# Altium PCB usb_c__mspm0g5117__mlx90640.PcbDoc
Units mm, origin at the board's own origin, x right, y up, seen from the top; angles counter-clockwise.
Board outline 64 x 33 mm, 2 copper layers (Top, Bottom), stack 0 mm thick; 27 components, 19 nets, 155 pads, 66 vias.
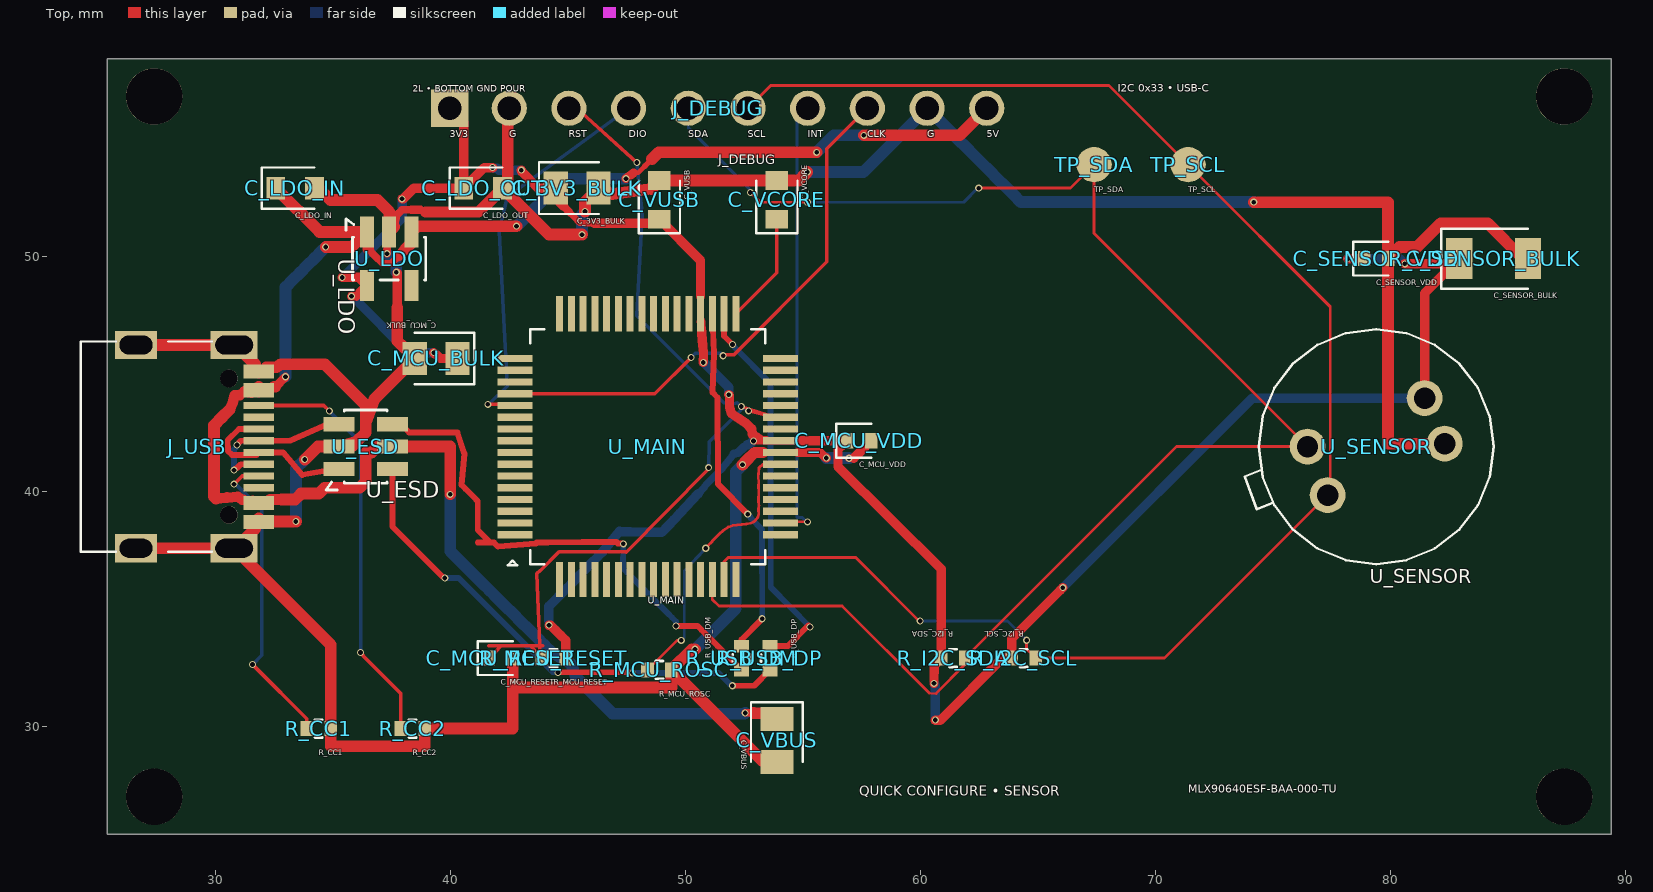
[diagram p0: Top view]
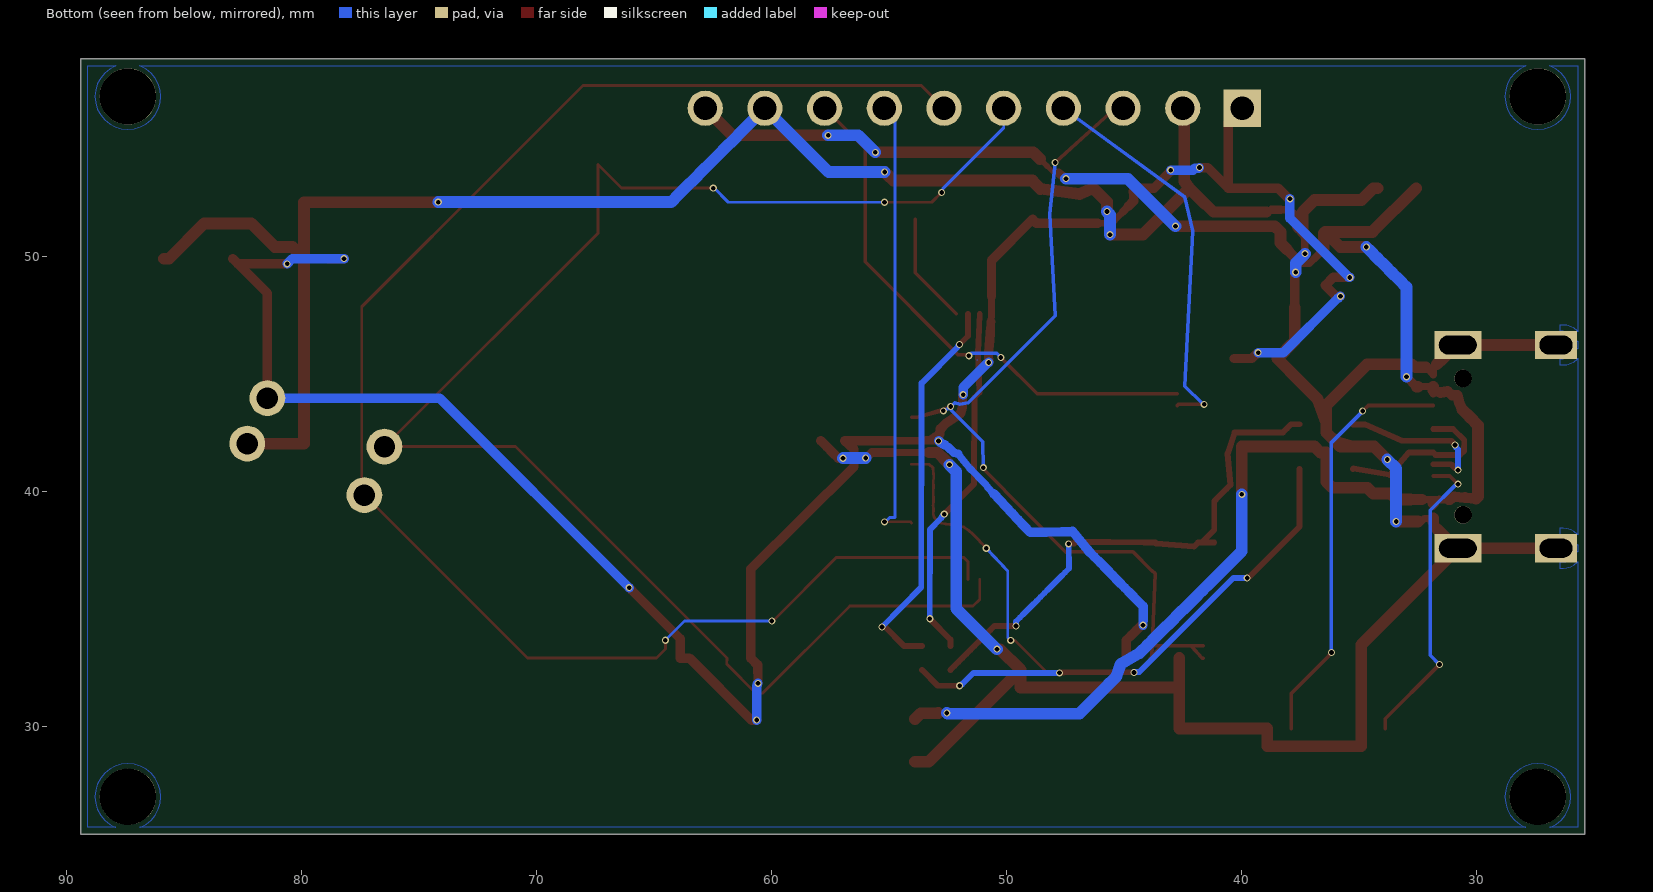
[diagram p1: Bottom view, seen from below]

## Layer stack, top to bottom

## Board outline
25.4,58.4 89.4,58.4 89.4,25.4 25.4,25.4

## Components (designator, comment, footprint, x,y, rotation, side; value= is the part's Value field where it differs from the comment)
C_3V3_BULK "" TSCIRCUIT-2.8500x1.4000mm 45.4,52.9 r0 top
C_LDO_IN "" TSCIRCUIT-2.4500x0.9500mm 33.4,52.9 r0 top
C_LDO_OUT "" TSCIRCUIT-2.4500x0.9500mm 41.4,52.9 r0 top
C_MCU_BULK "" TSCIRCUIT-2.8500x1.4000mm 39.4,45.65 r180 top
C_MCU_RESET "" TSCIRCUIT-1.5600x0.6400mm 42.15,32.9 r0 top
C_MCU_VDD "" TSCIRCUIT-1.5600x0.6400mm 57.4,42.15 r0 top
C_SENSOR_BULK "" TSCIRCUIT-4.0500x1.7500mm 84.4,49.9 r0 top
C_SENSOR_VDD "" TSCIRCUIT-1.5600x0.6400mm 79.4,49.9 r0 top
C_VBUS "" TSCIRCUIT-1.4000x2.8500mm 53.9,29.4 r270 top
C_VCORE "" TSCIRCUIT-0.9500x2.4500mm 53.9,52.4 r90 top
C_VUSB "" TSCIRCUIT-0.9500x2.4500mm 48.9,52.4 r90 top
J_DEBUG "" TSCIRCUIT-24.3600x1.5000mm 51.4,56.3 r0 top
J_USB "" TSCIRCUIT-6.7732x9.8502mm 29.112,41.9 r90 top
R_CC1 "" TSCIRCUIT-1.5600x0.6400mm 34.4,29.9 r0 top
R_CC2 "" TSCIRCUIT-1.5600x0.6400mm 38.4,29.9 r0 top
R_I2C_SCL "" TSCIRCUIT-1.5600x0.6400mm 64.4,32.9 r180 top
R_I2C_SDA "" TSCIRCUIT-1.5600x0.6400mm 61.4,32.9 r180 top
R_MCU_RESET "" TSCIRCUIT-1.5600x0.6400mm 44.4,32.9 r0 top
R_MCU_ROSC "" TSCIRCUIT-1.5600x0.6400mm 48.9,32.4 r0 top
R_USB_DM "" TSCIRCUIT-0.6400x1.5600mm 52.4,32.9 r90 top
R_USB_DP "" TSCIRCUIT-0.6400x1.5600mm 53.6,32.9 r90 top
TP_SCL "" TSCIRCUIT-1.5000x1.5000mm 71.4,53.9 r0 top
TP_SDA "" TSCIRCUIT-1.5000x1.5000mm 67.4,53.9 r0 top
U_ESD "" TSCIRCUIT-3.6000x2.5000mm 36.4,41.9 r0 top
U_LDO "" TSCIRCUIT-2.5000x3.6000mm 37.4,49.9 r270 top
U_MAIN "" TSCIRCUIT-12.8000x12.8000mm 48.4,41.9 r0 top
U_SENSOR "" TSCIRCUIT-7.3640x5.6538mm 79.4,41.9 r0 top

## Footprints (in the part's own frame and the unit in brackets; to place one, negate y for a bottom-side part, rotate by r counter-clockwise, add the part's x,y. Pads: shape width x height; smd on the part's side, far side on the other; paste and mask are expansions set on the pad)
TSCIRCUIT-0.6400x1.5600mm [mm]
  rect 0.54x0.64 smd: 1(-0.51,0) 2(0.51,0)
  silkscreen extent -0.15,-0.38 0.15,0.38
TSCIRCUIT-0.9500x2.4500mm [mm]
  rect 0.8x0.95 smd: 1(-0.825,0) 2(0.825,0)
  silkscreen extent -1.42,-0.88 0.82,0.87
TSCIRCUIT-1.4000x2.8500mm [mm]
  rect 1.025x1.4 smd: 1(-0.913,0) 2(0.913,0)
  silkscreen extent -1.63,-1.1 0.91,1.1
TSCIRCUIT-1.5000x1.5000mm [mm]
  round 1.5 smd: 1(0,0)
TSCIRCUIT-1.5600x0.6400mm [mm]
  rect 0.54x0.64 smd: 1(-0.51,0) 2(0.51,0)
  silkscreen extent -0.98,-0.72 0.51,0.72
TSCIRCUIT-2.4500x0.9500mm [mm]
  rect 0.8x0.95 smd: 1(-0.825,0) 2(0.825,0)
  silkscreen extent -1.42,-0.88 0.82,0.87
TSCIRCUIT-2.5000x3.6000mm [mm]
  rect 1.325x0.6 smd: 1(-1.138,-0.95) 2(-1.138,0) 3(-1.138,0.95) 4(1.137,0.95) 5(1.137,-0.95)
  silkscreen extent -1.69,-1.84 0.91,1.56
TSCIRCUIT-2.8500x1.4000mm [mm]
  rect 1.025x1.4 smd: 1(-0.913,0) 2(0.913,0)
  silkscreen extent -1.63,-1.1 0.91,1.1
TSCIRCUIT-3.6000x2.5000mm [mm]
  rect 1.325x0.6 smd: 1(-1.138,-0.95) 2(-1.138,0) 3(-1.138,0.95) 4(1.137,0.95) 5(1.137,0) 6(1.137,-0.95)
  silkscreen extent -1.69,-1.84 0.91,1.56
TSCIRCUIT-4.0500x1.7500mm [mm]
  rect 1.125x1.75 smd: 1(-1.462,0) 2(1.463,0)
  silkscreen extent -2.22,-1.27 1.46,1.28
TSCIRCUIT-6.7732x9.8502mm [mm]
  rect 0.3x1.3 smd: 1(-3.35,-2.737) 2(-3.05,-2.737) 3(-2.55,-2.737) 4(-2.25,-2.737) 5(-1.75,-2.737) 6(-1.25,-2.737) 7(-0.75,-2.737) 8(-0.25,-2.737) 9(0.25,-2.737) 10(0.75,-2.737) 11(1.25,-2.737) 12(1.75,-2.737) 13(2.55,-2.737) 14(2.25,-2.737) 15(3.35,-2.737) 16(3.05,-2.737)
  rect 1.2x2 hole 0.8 slot 1.6 at 90 deg: 17(-4.325,-1.693) 18(4.325,-1.693)
  rect 1.2x1.8 hole 0.8 slot 1.4 at 90 deg: 19(4.325,2.487) 20(-4.325,2.487)
  round 0.75 hole 0.75 unplated: NPTH-1(-2.9,-1.468) NPTH-2(2.9,-1.468)
  silkscreen extent -4.47,-0.75 4.47,4.83
TSCIRCUIT-7.3640x5.6538mm [mil]
  round 60 hole 36: 1(-114.96,0.01) 2(81.29,81.3) 3(114.96,5.01) 4(-81.3,-81.29)
  silkscreen extent -220,-197 197,197
TSCIRCUIT-12.8000x12.8000mm [mm]
  rect 1.5x0.3 smd: 1(-5.65,-3.75) 2(-5.65,-3.25) 3(-5.65,-2.75) 4(-5.65,-2.25) 5(-5.65,-1.75) 6(-5.65,-1.25) 7(-5.65,-0.75) 8(-5.65,-0.25) 9(-5.65,0.25) 10(-5.65,0.75) 11(-5.65,1.25) 12(-5.65,1.75) 13(-5.65,2.25) 14(-5.65,2.75) 15(-5.65,3.25) 16(-5.65,3.75) 33(5.65,3.75) 34(5.65,3.25) 35(5.65,2.75) 36(5.65,2.25) 37(5.65,1.75) 38(5.65,1.25) 39(5.65,0.75) 40(5.65,0.25) 41(5.65,-0.25) 42(5.65,-0.75) 43(5.65,-1.25) 44(5.65,-1.75) 45(5.65,-2.25) 46(5.65,-2.75) 47(5.65,-3.25) 48(5.65,-3.75)
  rect 0.3x1.5 smd: 17(-3.75,5.65) 18(-3.25,5.65) 19(-2.75,5.65) 20(-2.25,5.65) 21(-1.75,5.65) 22(-1.25,5.65) 23(-0.75,5.65) 24(-0.25,5.65) 25(0.25,5.65) 26(0.75,5.65) 27(1.25,5.65) 28(1.75,5.65) 29(2.25,5.65) 30(2.75,5.65) 31(3.25,5.65) 32(3.75,5.65) 49(3.75,-5.65) 50(3.25,-5.65) 51(2.75,-5.65) 52(2.25,-5.65) 53(1.75,-5.65) 54(1.25,-5.65) 55(0.75,-5.65) 56(0.25,-5.65) 57(-0.25,-5.65) 58(-0.75,-5.65) 59(-1.25,-5.65) 60(-1.75,-5.65) 61(-2.25,-5.65) 62(-2.75,-5.65) 63(-3.25,-5.65) 64(-3.75,-5.65)
  silkscreen extent -5.95,-5.05 5,5
TSCIRCUIT-24.3600x1.5000mm [mm]
  rect 1.6x1.6 hole 1: 1(-11.43,0)
  round 1.5 hole 1: 2(-8.89,0) 3(-6.35,0) 4(-3.81,0) 5(-1.27,0) 6(1.27,0) 7(3.81,0) 8(6.35,0) 9(8.89,0) 10(11.43,0)

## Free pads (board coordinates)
  round 2.4 hole 2.4 unplated: NPTH-3(27.4,27) NPTH-4(87.4,27) NPTH-5(27.4,56.8) NPTH-6(87.4,56.8)

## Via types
v1: diameter 0.3, hole 0.2, Top to Bottom, 66 vias

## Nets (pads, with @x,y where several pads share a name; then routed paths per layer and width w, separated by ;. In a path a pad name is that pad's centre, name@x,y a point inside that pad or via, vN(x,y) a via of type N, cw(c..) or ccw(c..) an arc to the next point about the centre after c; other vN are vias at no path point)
".J_DEBUG > .pin4 to .U_MAIN > .pin12": J_DEBUG.4 U_MAIN.12 | length 16.8
  Top w0.15: v1(41.6,43.7) 42.7,43.7 U_MAIN.12
  Bottom w0.15: v1(41.6,43.7) 41.623,43.723 41.666,43.723 42.419,44.476 42.082,51.07 42.419,52.521 J_DEBUG.4
".J_DEBUG > .pin8 to .U_MAIN > .pin13": J_DEBUG.8 U_MAIN.13 | length 22.9
  Top w0.15: U_MAIN.13 48.704,44.15 v1(50.249,45.695) ; v1(51.611,45.767) 51.662,45.818 52.081,45.818 56.027,49.764 56.027,54.577 J_DEBUG.8
  Bottom w0.15: v1(50.249,45.695) 50.424,45.87 51.508,45.87 v1(51.611,45.767)
".U_MAIN > .pin42 to .R_MCU_ROSC > .pin1": R_MCU_ROSC.1 U_MAIN.42 | length 12.1
  Top w0.12: R_MCU_ROSC.1 49.645,33.655 v1(49.83,33.655) ; v1(50.872,37.575) 51.059,37.775 51.234,37.975 51.426,38.167 51.627,38.34 51.826,38.477 52.014,38.538 52.206,38.57 52.401,38.59 52.596,38.608 52.78,38.638 52.937,38.712 53.07,38.859 53.125,39.025 53.118,39.21 53.131,39.399 53.117,39.598 53.125,39.998 53.118,40.2 53.131,40.397 53.106,40.601 53.143,41.004 53.3,41.15 U_MAIN.42
  Bottom w0.12: v1(49.83,33.655) 49.851,33.676 49.959,33.784 49.959,33.874 49.959,36.613 v1(50.872,37.575)
GND: C_3V3_BULK.2 C_LDO_IN.2 C_LDO_OUT.2 C_MCU_BULK.2 C_MCU_RESET.2 C_MCU_VDD.2 C_SENSOR_BULK.2 C_SENSOR_VDD.2 C_VBUS.2 C_VCORE.2 C_VUSB.2 J_DEBUG.2 J_DEBUG.9 J_USB.1 J_USB.2 J_USB.15 J_USB.16 J_USB.17 J_USB.18 J_USB.19 J_USB.20 R_CC1.2 R_CC2.2 R_MCU_ROSC.2 U_ESD.2 U_LDO.2 U_MAIN.41 U_SENSOR.3 | length 166.6
  Top w0.275: J_USB.16 J_USB.15@32.173,45.274
  Top w0.3: J_USB.1@31.699,38.4 J_USB.1 J_USB.1@31.849,38.7 ; 31.699,45.4 J_USB.15 J_USB.16@31.849,45.1 ; J_USB.2 31.945,38.839 32.037,38.85 32.13,38.85 32.224,38.85 32.36,38.714 J_USB.2@32.499,38.714 ; 53.3,41.65 53.394,41.65 53.488,41.65 53.581,41.65 53.675,41.65 53.769,41.65 53.863,41.65 53.956,41.65 U_MAIN.41 54.144,41.65 54.237,41.65 54.331,41.65 54.425,41.65 54.519,41.65 54.612,41.65 54.706,41.65 U_MAIN.41@54.8,41.65
  Top w0.31: J_USB.16 J_USB.16@31.849,45.1
  Top w0.325: v1(37.306,50.111) 37.321,50.543 U_LDO.2@37.337,50.974 ; U_LDO.2@37.616,51.253 37.713,51.744 37.947,51.978 38.338,51.978 ; v1(37.705,49.32) v1@37.743,49.289 ; v1(56.97,41.405) 57.165,41.405
  Top w0.35: 38.338,51.978 38.728,51.978 38.959,51.878
  Top w0.375: U_MAIN.41@54.8,41.65 55.274,41.65 55.748,41.65 55.961,41.437 55.987,41.437 v1(56.005,41.419)
  Top w0.4: 37.743,47.816 37.743,48.29 37.743,48.764 37.743,49.238 v1@37.743,49.289 ; 57.165,41.405 57.413,41.653 57.662,41.902 C_MCU_VDD.2
  Top w0.475: U_LDO.2 U_LDO.2@37.616,51.253 ; 38.959,51.878 39.408,51.878 39.857,51.878 40.306,51.878 40.755,51.878 41.203,51.878 41.544,52.219 ; 52.716,41.422 52.944,41.65 53.3,41.65
  Top w0.5: J_USB.20 J_USB.17 ; J_USB.19 J_USB.18 ; J_USB.18 30.874,46.225 31.474,45.625 31.699,45.4 ; J_USB.1@31.699,38.4 31.474,38.175 30.874,37.575 J_USB.17 34.91,33.471 R_CC1.2 34.91,29.15 38.91,29.15 R_CC2.2 42.66,29.9 C_MCU_RESET.2 42.66,31.775 42.785,31.65 48.9,31.65 49.41,31.65 R_MCU_ROSC.2 ; J_USB.1@31.849,38.7 J_USB.2 ; J_USB.15@32.173,45.274 32.607,45.274 32.775,45.4 34.664,45.4 36.101,43.963 36.4,43.664 36.4,42.7 36.4,42.5 ; 32.499,38.714 v1(33.43,38.714) ; v1(33.806,41.348) 34.358,41.9 U_ESD.2 ; C_LDO_IN.2 34.4,52.9 34.9,52.4 36.9,52.4 37.4,51.9 U_LDO.2 U_LDO.2@37.337,50.975 ; 37.743,47.816 37.743,47.342 37.743,46.869 37.743,46.395 37.991,46.146 38.239,45.898 C_MCU_BULK.2 38.146,45.309 37.805,44.968 37.464,44.627 37.123,44.286 36.782,43.945 36.4,42.9 36.4,42.5 ; 41.544,52.219 41.884,52.559 C_LDO_OUT.2 ; J_DEBUG.2 42.45,56.24 42.45,53.185 C_LDO_OUT.2 ; v1(45.604,50.922) 44.203,50.922 C_LDO_OUT.2 ; v1(45.735,51.903) 45.735,52.323 C_3V3_BULK.2 46.9,52.65 48.575,52.868 48.9,53.193 C_VUSB.2 C_VCORE.2 54.827,53.225 55.036,53.434 55.045,53.434 v1(55.195,53.584) ; v1(50.418,33.279) 50.289,33.279 49.996,32.986 49.703,32.693 R_MCU_ROSC.2 ; v1(52.439,41.131) 52.489,41.181 52.489,41.195 52.716,41.422 ; C_VBUS.2 53.322,28.487 R_MCU_ROSC.2 ; v1(74.192,52.304) 74.665,52.304 79.91,52.304 C_SENSOR_VDD.2 ; U_SENSOR.3 79.91,42.027 79.91,48.473 79.91,48.949 79.91,49.424 C_SENSOR_VDD.2 ; C_SENSOR_BULK.2 85.65,49.9 84.15,51.4 82.15,51.4 81.15,50.4 80.4,50.4 79.9,49.9 C_SENSOR_VDD.2 ; U_ESD.2 35.8,41.9 36,42.1 ; U_ESD.2 36,42.1 ; 36,42.1 36.4,42.5 ; 36,42.1 36.4,42.5
  Bottom w0.5: v1(33.43,38.714) 33.43,40.972 v1(33.806,41.348) ; v1(37.306,50.111) 37.705,49.712 v1(37.705,49.32) ; v1(45.604,50.922) 45.604,51.772 v1(45.735,51.903) ; v1(50.418,33.279) 52.148,35.009 52.148,40.838 v1(52.439,41.131) ; v1(55.195,53.584) 57.574,53.584 J_DEBUG.9 60.623,55.967 60.956,55.634 61.289,55.301 61.622,54.968 61.955,54.635 62.287,54.303 62.62,53.97 62.953,53.637 63.286,53.304 63.619,52.971 63.952,52.638 64.285,52.305 64.776,52.305 65.267,52.305 65.759,52.305 66.25,52.305 66.741,52.305 67.232,52.305 67.723,52.305 68.215,52.305 68.706,52.305 69.197,52.305 69.688,52.305 70.179,52.305 70.671,52.305 71.162,52.305 71.653,52.305 72.144,52.305 72.635,52.305 73.127,52.305 73.618,52.305 74.109,52.305 74.191,52.305 v1(74.192,52.304) ; v1(56.005,41.419) 56.956,41.419 v1(56.97,41.405)
MAIN_RESET: C_MCU_RESET.1 J_DEBUG.3 R_MCU_RESET.1 U_MAIN.38 | length 41.2
  Top w0.15: C_MCU_RESET.1 41.68,32.9 42.16,33.425 41.64,33.425 43.939,33.425 43.16,33.425 43.41,33.425 R_MCU_RESET.1 43.828,32.962 43.675,36.5 43.828,36.624 44.628,37.424 47.458,37.419 47.491,37.407 50.959,40.909 50.958,40.937 v1(50.995,41.002) ; J_DEBUG.3 45.391,56.3 v1(47.942,53.992) ; v1(52.387,43.609) U_MAIN.38@53.809,43.15 ; v1(52.7,43.425) U_MAIN.38@53.809,43.15 ; U_MAIN.38@53.809,43.15 U_MAIN.38 U_MAIN.38@53.809,43.15
  Bottom w0.15: v1(47.942,53.992) 48.175,51.8 47.942,47.471 51.639,43.771 52,43.7 52.206,43.772 52.334,43.646 52.35,43.646 v1(52.387,43.609) ; v1(50.995,41.002) 51.023,42.114 52.357,43.447 52.357,43.579 v1(52.7,43.425)
MSP_VCORE: C_VCORE.1 U_MAIN.32 | length 4.7
  Top w0.15: U_MAIN.32 53.9,49.3 C_VCORE.1
SENSOR_INT: J_DEBUG.7 U_MAIN.47 | length 19.3
  Top w0.12: U_MAIN.47 54.1,38.7 v1(55.2,38.7)
  Bottom w0.12: v1(55.2,38.7) 55.173,38.727 55.135,38.727 54.981,38.881 54.749,38.881 54.749,55.839 J_DEBUG.7
SENSOR_SCL: J_DEBUG.6 R_I2C_SCL.1 TP_SCL.1 U_MAIN.50 U_SENSOR.4 | length 68.5
  Top w0.12: U_MAIN.50 51.65,37 51.827,37.177 57.253,37.177 59.944,34.485 59.996,34.485 v1(59.999,34.482) ; J_DEBUG.6 53.641,57.271 68.018,57.271 68.029,57.271 TP_SCL.1 77.45,47.85 77.45,40.037 77.45,39.95 U_SENSOR.4 70.4,32.9 R_I2C_SCL.1 64.528,33.282 v1(64.528,33.661)
  Bottom w0.12: v1(59.999,34.482) 63.707,34.482 64.474,33.715 v1(64.528,33.661)
SENSOR_SDA: J_DEBUG.5 R_I2C_SDA.1 TP_SDA.1 U_MAIN.51 U_SENSOR.1 | length 68.3
  Top w0.12: U_MAIN.51 51.15,35.397 51.43,35.116 56.677,35.116 60.391,31.402 60.677,31.387 61.912,32.648 R_I2C_SDA.1 70.91,41.9 U_SENSOR.1 67.4,50.98 TP_SDA.1 66.4,52.9 v1(62.49,52.9) ; v1(52.772,52.71) 53.191,52.3 55.097,52.3 v1(55.2,52.3)
  Bottom w0.12: J_DEBUG.5 50.13,55.468 52.724,52.874 52.724,52.767 v1(52.772,52.71) ; v1(55.2,52.3) 61.85,52.3 62.45,52.899 v1@62.489,52.899
usb-dm-mcu: R_USB_DM.2 U_MAIN.30 | length 15.4
  Top w0.25: U_MAIN.30 51.222,45.875 51.167,44.2 51.37,43.985 51.388,40.319 v1(52.66,39.024) ; R_USB_DM.2 52.4,33.691 53.261,34.552 v1(53.274,34.574)
  Bottom w0.25: v1(52.66,39.024) 52.784,38.9 52.784,38.866 53.27,38.367 v1(53.274,34.574)
usb-dm-phy: R_USB_DM.1 U_ESD.4 | length 23
  Top w0.25: U_ESD.4 37.72,42.85 37.902,42.85 38.074,42.678 38.246,42.506 40.3,42.5 40.6,41.6 40.484,40.269 40.656,40.097 40.828,39.924 41,39.752 41.172,39.58 41.172,39.334 41.172,39.088 41.172,38.842 41.172,38.596 41.172,38.349 41.342,38.18 41.512,38.01 41.681,37.84 41.512,37.835 41.342,37.83 41.172,37.825 41.4,37.825 41.628,37.825 41.856,37.825 42.025,37.65 43.65,37.775 43.681,37.825 43.923,37.826 44.166,37.827 44.408,37.828 44.65,37.829 44.892,37.83 45.134,37.831 45.376,37.833 45.618,37.834 45.86,37.835 46.102,37.836 46.344,37.837 46.586,37.838 46.829,37.839 47.071,37.84 47.126,37.785 47.336,37.785 v1(47.365,37.763) ; v1(49.603,34.263) 49.834,34.263 50.065,34.263 50.296,34.263 50.527,34.263 50.697,34.093 50.868,33.922 51.038,33.752 51.208,33.582 51.378,33.412 51.549,33.241 51.719,33.071 51.889,32.901 52.059,32.731 52.23,32.56 R_USB_DM.1
  Bottom w0.25: v1(47.365,37.763) 47.362,37.553 47.359,37.343 47.356,37.133 47.353,36.923 47.35,36.713 47.523,36.539 47.697,36.366 47.87,36.192 48.044,36.019 48.217,35.845 48.391,35.672 48.564,35.498 48.738,35.325 48.911,35.151 49.085,34.978 49.258,34.804 49.432,34.631 49.605,34.457 49.605,34.265 v1(49.603,34.263)
usb-dm-port: J_USB.7 J_USB.9 U_ESD.3 | length 6.9
  Top w0.25: v1(30.799,40.9) 30.88,40.981 30.919,40.981 31.088,41.15 J_USB.7 ; v1(30.923,41.97) 31.083,42.15 J_USB.9 33.178,42.15 34.764,42.849 U_ESD.3
  Bottom w0.25: v1(30.799,40.9) 30.799,41.787 30.878,41.866 30.878,41.945 v1(30.923,41.97)
usb-dp-mcu: R_USB_DP.2 U_MAIN.31 | length 16.9
  Top w0.25: U_MAIN.31 51.65,46.606 v1(52.014,46.242) ; R_USB_DP.2 54.363,33.41 55.237,34.285 55.249,34.285 v1(55.31,34.224)
  Bottom w0.25: v1(52.014,46.242) 52.086,46.17 52.086,46.136 53.62,44.602 53.622,44.522 53.64,35.914 v1(55.31,34.224)
usb-dp-phy: R_USB_DP.1 U_ESD.6 | length 21.6
  Top w0.25: U_ESD.6 37.537,38.495 39.69,36.342 39.736,36.342 v1(39.768,36.31) ; v1(44.587,32.287) 47.57,32.3 47.59,32.28 47.747,32.28 v1(47.753,32.274) ; v1(52.006,31.724) 52.934,31.724 R_USB_DP.1
  Bottom w0.25: v1(39.768,36.31) 40.355,36.31 44.359,32.306 44.594,32.306 v1(44.587,32.287) ; v1(47.753,32.274) 51.415,32.274 51.909,31.78 51.95,31.78 v1(52.006,31.724)
usb-dp-port: J_USB.8 J_USB.10 U_ESD.1 | length 7.3
  Top w0.25: J_USB.10 31.01,42.65 30.532,42.183 30.534,41.714 30.71,41.547 31.746,41.547 J_USB.8 32.887,41.65 33.7,40.7 35.243,40.967 U_ESD.1
USB_CC1: J_USB.6 R_CC1.1 | length 13.2
  Top w0.15: v1(30.799,40.3) 31.149,40.65 J_USB.6 ; v1(31.585,32.624) 31.71,32.499 31.714,32.499 33.89,30.323 R_CC1.1
  Bottom w0.15: v1(30.799,40.3) 30.853,40.246 30.922,40.246 31.982,39.186 31.982,33.021 v1(31.585,32.624)
USB_CC2: J_USB.12 R_CC2.1 | length 17.9
  Top w0.15: J_USB.12 34.62,43.65 v1(34.851,43.419) ; v1(36.181,33.135) 36.295,33.021 36.295,32.989 37.89,31.395 R_CC2.1
  Bottom w0.15: v1(34.851,43.419) 34.904,43.366 34.904,43.355 36.181,42.077 v1(36.181,33.135)
VBUS5: C_LDO_IN.1 C_VBUS.1 J_DEBUG.10 J_USB.3 J_USB.4 J_USB.13 J_USB.14 U_ESD.5 U_LDO.1 U_LDO.3 | length 84.1
  Top w0.2: 47.794,53.554 48,53.554 48.29,53.844
  Top w0.25: 48.29,53.844 48.58,54.135
  Top w0.275: J_USB.3 J_USB.3@31.849,39.5
  Top w0.3: J_USB.14@31.546,44.197 J_USB.14 J_USB.14@31.849,44.3 ; J_USB.4@31.593,39.65 J_USB.4 ; J_USB.3@31.849,39.5 J_USB.4 ; J_USB.13 31.943,44.45 32.037,44.45 32.13,44.45 32.224,44.45 32.318,44.45 32.412,44.45 32.499,44.45 ; J_USB.4@32.332,39.65 J_USB.4
  Top w0.312: 36.813,50.001 37.118,49.69 37.482,49.69 37.774,49.981
  Top w0.325: 36.508,50.312 36.813,50.001 ; v1(52.549,30.568) 52.919,30.563
  Top w0.331: J_USB.4@31.199,39.641 J_USB.4@31.593,39.65
  Top w0.35: v1@32.944,44.825 v1(32.992,44.873)
  Top w0.375: 32.569,44.45 32.59,44.471 v1@32.944,44.825 ; v1(47.481,53.303) 47.794,53.554
  Top w0.425: 37.774,49.981 38.064,50.28
  Top w0.437: 30.822,44.087 31.041,44.087 J_USB.14@31.244,44.244 ; 30.963,39.775 31.15,39.64 31.199,39.641
  Top w0.45: 30.033,39.692 30.498,39.733 30.963,39.775 ; 30.618,43.48 30.743,43.768 30.822,44.087
  Top w0.475: J_USB.14@31.244,44.244 J_USB.14@31.546,44.197 ; J_USB.13@31.849,44.3 J_USB.13 ; J_USB.4@32.332,39.65 32.814,39.65 ; 32.499,44.45 32.505,44.45 32.569,44.45 ; 36.508,50.312 U_LDO.1@36.508,50.645
  Top w0.5: 30.033,39.692 29.947,39.778 29.947,42.809 30.282,43.145 30.618,43.48 ; C_LDO_IN.1 34.438,51.038 U_LDO.1 ; 32.814,39.65 33.297,39.65 33.4,39.65 33.65,39.9 34.4,39.9 34.65,40.15 36.15,40.15 36.4,40.4 36.4,41.65 36.65,41.65 36.9,41.9 U_ESD.5 39.998,41.9 v1(39.998,39.869) ; v1(34.698,50.394) 35.806,50.394 U_LDO.1 ; U_LDO.1@36.508,50.645 36.508,50.979 U_LDO.1 ; 38.064,50.28 38.354,50.579 U_LDO.3 38.596,51.283 v1(42.822,51.283) ; 48.58,54.135 48.871,54.425 49.351,54.425 49.831,54.425 50.311,54.425 50.791,54.425 51.271,54.425 51.751,54.425 52.231,54.425 52.711,54.425 53.191,54.425 53.671,54.425 54.151,54.425 54.631,54.425 55.111,54.425 v1(55.591,54.425) ; 52.919,30.563 53.288,30.559 53.658,30.554 C_VBUS.1 ; v1(57.602,55.149) 61.679,55.149 J_DEBUG.10
  Bottom w0.5: v1(32.992,44.873) 32.992,45.35 32.992,45.827 32.992,46.304 32.992,46.781 32.992,47.258 32.992,47.735 32.992,48.211 32.992,48.688 33.301,48.997 33.61,49.306 33.919,49.615 34.227,49.923 34.536,50.232 v1(34.698,50.394) ; v1(39.998,39.869) 39.998,39.384 39.998,38.899 39.998,38.414 39.998,37.93 39.998,37.445 40.333,37.112 40.667,36.779 41.001,36.447 41.336,36.114 41.67,35.781 42.004,35.449 42.339,35.116 42.673,34.784 43.007,34.451 43.342,34.118 43.676,33.786 44.01,33.453 44.345,33.12 45.15,32.65 45.329,32.135 45.645,31.815 45.96,31.495 46.276,31.175 46.592,30.855 46.907,30.535 47.375,30.535 47.842,30.535 48.31,30.535 48.777,30.535 49.244,30.535 49.712,30.535 50.179,30.535 50.646,30.535 51.114,30.535 51.581,30.535 52.049,30.535 52.516,30.535 v1(52.549,30.568) ; v1(42.822,51.283) 44.842,53.303 v1(47.481,53.303) ; v1(55.591,54.425) 56.315,55.149 v1(57.602,55.149)
VCC_3V3: C_3V3_BULK.1 C_LDO_OUT.1 C_MCU_BULK.1 C_MCU_VDD.1 C_SENSOR_BULK.1 C_SENSOR_VDD.1 C_VUSB.1 J_DEBUG.1 R_I2C_SCL.2 R_I2C_SDA.2 R_MCU_RESET.2 U_LDO.5 U_MAIN.29 U_MAIN.40 U_SENSOR.2 | length 112
  Top w0.288: 45.054,51.891 45.28,51.661 45.505,51.43 45.748,51.404 46.121,51.405
  Top w0.3: 50.65,48.3 50.65,48.25 50.65,48.15 50.65,48.05 50.65,47.95 50.65,47.85 50.65,47.75 50.65,47.65 U_MAIN.29 U_MAIN.29@50.675,47.213 ; v1(52.901,42.143) 53.282,42.143 53.662,42.143 54.043,42.143 U_MAIN.40 ; U_MAIN.40@53.688,42.15 U_MAIN.40 ; U_MAIN.40@54.8,42.15 54.75,42.15 54.65,42.15 54.55,42.15 54.45,42.15 54.35,42.15 54.25,42.15 54.15,42.15 U_MAIN.40
  Top w0.312: U_MAIN.40@53.444,42.175 U_MAIN.40@53.688,42.15
  Top w0.325: 44.828,52.122 45.054,51.891
  Top w0.363: 53.2,42.2 U_MAIN.40@53.444,42.175
  Top w0.372: U_MAIN.29@50.675,47.213 U_MAIN.29@50.695,46.8
  Top w0.4: v1(35.4,49.1) 36.112,49.1 U_LDO.5 35.988,48.3 v1(35.8,48.3) ; v1(37.949,52.442) 37.961,52.454 38.01,52.454 38.456,52.9 C_LDO_OUT.1 ; v1(39.301,45.901) 39.369,45.833 39.388,45.833 39.571,45.65 C_MCU_BULK.1 ; J_DEBUG.1 40.575,55.695 C_LDO_OUT.1 ; v1(41.8,53.775) 41.45,53.775 C_LDO_OUT.1 ; v1(43.025,53.667) 43.041,53.604 43.733,52.9 C_3V3_BULK.1 44.612,52.776 44.607,52.564 44.602,52.353 44.828,52.122 ; v1(44.2,34.3) 44.266,34.3 44.48,34.085 44.695,33.87 44.91,33.656 44.91,33.278 R_MCU_RESET.2 ; 46.121,51.405 46.495,51.406 46.868,51.406 47.242,51.407 47.615,51.408 47.989,51.409 48.363,51.41 48.736,51.411 C_VUSB.1 50.65,49.825 50.65,48.35 50.65,48.3 ; 50.695,46.8 50.7,46.7 50.75,46.204 50.776,45.867 v1(50.77,45.483) ; v1(51.857,44.111) 51.884,44.079 51.884,43.835 51.884,43.592 51.975,43.3 52.274,43.102 52.573,42.904 52.824,42.652 52.85,42.425 53.025,42.313 53.2,42.2 ; 54.8,42.15 54.85,42.15 C_MCU_VDD.1 56.502,41.796 56.499,41.047 60.89,36.692 60.89,33.15 R_I2C_SDA.2 60.602,32.612 v1(60.584,31.828) ; v1(60.642,30.262) 60.647,30.257 60.859,30.257 63.503,32.9 R_I2C_SCL.2 63.89,33.72 65.962,35.792 v1(66.066,35.896) ; v1(78.2,49.9) 78.39,49.9 C_SENSOR_VDD.1 ; v1(80.624,49.68) 82.718,49.68 C_SENSOR_BULK.1 81.465,48.427 U_SENSOR.2
  Bottom w0.3: 50.803,40.16 50.9,40.3 51.125,40.526 51.35,40.752 51.575,40.978 51.825,41.289 52.075,41.6
  Bottom w0.312: 50.545,39.887 50.803,40.16
  Bottom w0.375: 52.075,41.6 52.242,41.637 52.464,41.857 52.645,41.971
  Bottom w0.4: v1(35.4,49.1) 35.416,49.116 35.449,49.116 37.949,51.616 v1(37.949,52.442) ; v1(35.8,48.3) 35.889,48.211 35.917,48.211 38.228,45.901 v1(39.301,45.901) ; v1(41.8,53.775) 41.834,53.741 41.998,53.741 42.072,53.667 v1(43.025,53.667) ; v1(44.2,34.3) 44.199,34.568 44.198,34.835 44.198,35.103 44.457,35.367 44.717,35.632 44.977,35.896 45.237,36.161 45.497,36.425 45.756,36.689 46.016,36.954 46.276,37.218 46.536,37.483 47.2,38.3 47.315,38.276 47.652,38.271 47.989,38.265 48.326,38.26 48.663,38.255 49,38.25 49.258,38.522 49.515,38.795 49.773,39.068 50.03,39.341 50.288,39.614 50.545,39.887 ; v1(50.77,45.483) 50.842,45.438 50.842,45.434 51.096,45.181 51.349,44.927 51.603,44.673 51.857,44.419 v1(51.857,44.111) ; 52.645,41.971 52.826,42.085 v1(52.901,42.143) ; v1(60.584,31.828) 60.612,31.8 60.612,31.749 60.642,31.719 v1(60.642,30.262) ; v1(66.066,35.896) 74.135,43.965 U_SENSOR.2 ; v1(78.2,49.9) 80.404,49.9 80.612,49.692 v1(80.624,49.68)
pads on no net: J_USB.5 J_USB.11 J_USB.NPTH-1 J_USB.NPTH-2 U_LDO.4 U_MAIN.1 U_MAIN.2 U_MAIN.3 U_MAIN.4 U_MAIN.5 U_MAIN.6 U_MAIN.7 U_MAIN.8 U_MAIN.9 U_MAIN.10 U_MAIN.11 U_MAIN.14 U_MAIN.15 U_MAIN.16 U_MAIN.17 U_MAIN.18 U_MAIN.19 U_MAIN.20 U_MAIN.21 U_MAIN.22 U_MAIN.23 U_MAIN.24 U_MAIN.25 U_MAIN.26 U_MAIN.27 U_MAIN.28 U_MAIN.33 U_MAIN.34 U_MAIN.35 U_MAIN.36 U_MAIN.37 U_MAIN.39 U_MAIN.43 U_MAIN.44 U_MAIN.45 U_MAIN.46 U_MAIN.48 U_MAIN.49 U_MAIN.52 U_MAIN.53 U_MAIN.54 U_MAIN.55 U_MAIN.56 U_MAIN.57 U_MAIN.58 U_MAIN.59 U_MAIN.60 U_MAIN.61 U_MAIN.62 U_MAIN.63 U_MAIN.64

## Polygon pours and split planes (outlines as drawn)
GND on Bottom (solid): 197 vertices, not listed, extent 25.7,25.7 89.1,58.1
GND on Bottom (solid): 51.251,45.595 51.247,45.595 51.257,45.585

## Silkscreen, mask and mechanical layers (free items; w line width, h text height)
Top Overlay:
  text "2L • BOTTOM GND POUR" at 38.4,56.9 h0.48
  text "I2C 0x33 • USB-C" at 68.4,56.9 h0.55
  text "MLX90640ESF-BAA-000-TU" at 71.4,27.05 h0.58
  text "QUICK CONFIGURE • SENSOR" at 57.4,26.9 h0.72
